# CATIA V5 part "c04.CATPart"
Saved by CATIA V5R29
Part number: c04
Source: Unknown
Bounding box of the stored display mesh (mm): x -18 to 0, y -67.553 to 154.447, z -197.568 to -77.568
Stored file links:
  C:\Users\Administrator\Desktop\프로젝트\Boxfold\TapeCutter\c04.CATPart
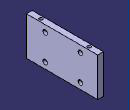
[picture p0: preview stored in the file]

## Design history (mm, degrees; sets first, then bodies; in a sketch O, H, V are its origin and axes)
Body1 (main body)
  Solid1 "PartBody": solid without history
  DatumCurve1
  DatumCurve2
  Sketch1 on face of Solid1, origin (0, 55.2, -128.6598), H (0, 1, 0), V (0, 0, 1)
    point P1 (45.2369, 30.2422)
    reference projected line E1 (219.7473, 30.2422) -> (-220.2527, 30.2422) from edge of DatumCurve1
    reference projected line E2 (65.2369, 21.0922) -> (65.2369, 104.0922) from edge of DatumCurve2
    distance P1 E2 = 20
    coincidence: P1 E1
  Hole1: placed by Sketch1, at (0, 100.4369, -98.4176) direction (-1, 0, 0), diameter 8.6, through (limit type 6), counterbore diameter 14, counterbore depth 8.6
  Sketch2 on face of Solid1, origin (0, -67.5527, -87.5676), H (0, 1, 0), V (-1, 0, 0)
    projected circle E2 centre (36, 9) radius 5.15 from face of Solid1
    projected circle E3 centre (186, 9) radius 5.15 from face of Solid1
  Pad1: profile Sketch2, direction (0, 0, 1), length 10
  Sketch3 on face of Solid1, origin (0, 154.4473, -187.5676), H (0, -1, 0), V (-1, 0, 0)
  Pad2: profile Sketch3, direction (0, 0, -1), length 10
  RectPattern1: of Hole1, direction 1 instances 2, spacing 110, along edge [face of Pad2 | end face of Pad1] reversed, direction 2 instances 2, spacing 80, along edge [face of Pad2 | face of Pad2] reversed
